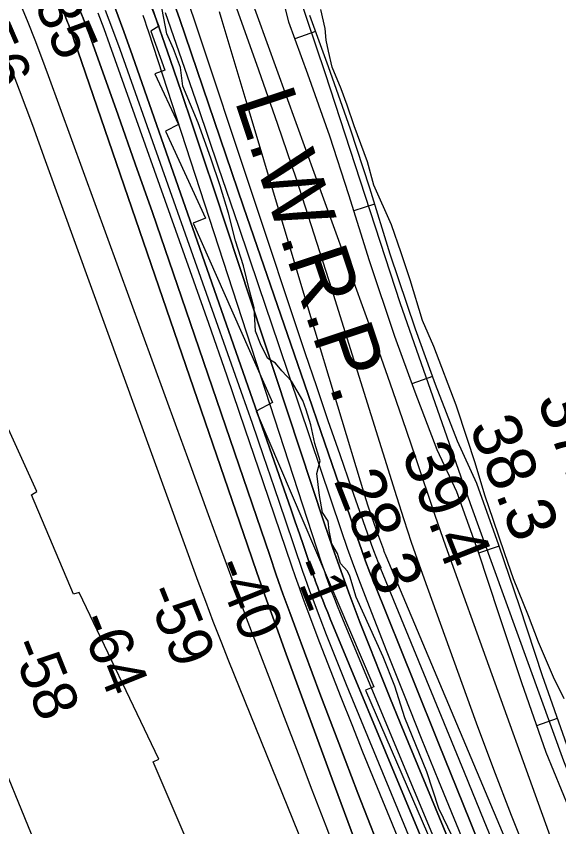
# Model space of a CAD drawing. Extents: x 3245246 to 3283090, y 806824 to 832173.
# Drawn here: x 3273263 to 3274008, y 812906 to 814018 of the extents above; entities that cross this region are included whole.
import ezdxf

# ---------------------------------------------------------------- set-up
doc = ezdxf.new("R2010")
doc.units = 0
for name, color, linetype in [('V-RIVR-EDGE', 7, 'Continuous'), ('V-RIVR-RANG', 7, 'Continuous'), ('V-ROAD-CNTR', 7, 'Continuous'), ('V-RRAP-RVMT', 7, 'Continuous'), ('V-SITE-VEGE', 7, 'Continuous'), ('V-TOPO-DPTH', 7, 'Continuous'), ('V-TOPO-MAJR', 7, 'Continuous'), ('V-TOPO-MINR', 7, 'Continuous'), ('V-TOPO-WATR', 7, 'Continuous'), ('V-TOPO-WATR-IDEN', 7, 'Continuous')]:
    doc.layers.add(name, color=color, linetype=linetype)

msp = doc.modelspace()

# ---------------------------------------------------------------- linework, layer by layer
at = {"layer": 'V-RIVR-EDGE'}
for points in [[(3273543.3, 813785.4), (3273530.4, 813823.2), (3273513.1, 813871.9), (3273491.9, 813922), (3273488.5, 813947.6), (3273479, 813973.3), (3273469.9, 813993.8), (3273461.4, 814039.4)], [(3273862.3, 812892.2), (3273843.3, 812930.9), (3273826.9, 812981.4), (3273796.7, 813055.3), (3273782.9, 813098.9), (3273766.9, 813139.3), (3273730.1, 813221.1), (3273721.1, 813249.8), (3273718.1, 813256.8), (3273708.5, 813267.3), (3273704.2, 813280.7), (3273696.4, 813294.2), (3273693, 813312.5), (3273691.3, 813325.1), (3273683.5, 813337.3), (3273679.6, 813360.3), (3273675.8, 813390.8), (3273680.6, 813408.2), (3273673.3, 813431.7), (3273667.7, 813457.3), (3273661.2, 813478.2), (3273656.5, 813490.8), (3273640.9, 813517.4), (3273627.9, 813531.7), (3273619.2, 813542.2), (3273608.8, 813548.7), (3273599.3, 813566.2), (3273591.5, 813586.2), (3273589.9, 813617.9), (3273583.4, 813641.8), (3273575.2, 813675.8), (3273564, 813710.1), (3273554.5, 813748), (3273543.3, 813785.4)]]:
    msp.add_lwpolyline(points, dxfattribs=at)
at = {"layer": 'V-ROAD-CNTR'}
for p, q in [((3273673.9, 813997.3), (3273645.8, 813987)), ((3273755.2, 813760.1), (3273726.5, 813751.2)), ((3273834.6, 813523.9), (3273806.4, 813513.6)), ((3273926.2, 813291.1), (3273897.8, 813281.5)), ((3274006.1, 813054.4), (3273977.8, 813044.4))]:
    msp.add_line(p, q, dxfattribs=at)
for points in [[(3272963.2, 815560), (3273122.6, 815224.6), (3273142.4, 815191.5), (3273353.7, 814953), (3273395.5, 814898.7), (3273440.1, 814822.1), (3273495.1, 814628), (3273529.1, 814569.5), (3273546.4, 814539.7), (3273596.6, 814463.2), (3273619.7, 814423.1), (3273629.1, 814390.7), (3273626, 814137.4), (3273649.7, 814051), (3273687.4, 813939.7), (3273789.9, 813625.3), (3273886.7, 813349.6), (3274014.5, 812996.5), (3274076.4, 812840.6), (3274213.5, 812549), (3274312.6, 812373.1), (3274357.1, 812286.8), (3274388.1, 812205.1)], [(3273619.3, 814081), (3273637.1, 814010.7), (3273663.2, 813939.3), (3273693.3, 813854), (3273719.6, 813773.4), (3273747.8, 813682.8), (3273782.6, 813579.1), (3273810.4, 813502.8), (3273840.9, 813423.6), (3273867.5, 813366.1), (3273897.3, 813283.1), (3273925.6, 813198.7), (3273956.8, 813104), (3273990.5, 813008.1), (3274022.2, 812931.4), (3274057.7, 812851.2), (3274092.4, 812770.8), (3274125.3, 812695.8), (3274162.2, 812620.9), (3274195.5, 812556.9), (3274241.3, 812467.3), (3274278, 812399.3), (3274306, 812345.1)], [(3273665.8, 814019.6), (3273691.4, 813949.4), (3273721.7, 813863.6), (3273748.2, 813782.5), (3273776.3, 813692), (3273810.9, 813589), (3273838.4, 813513.3), (3273868.5, 813435.3), (3273895.3, 813377.5), (3273925.6, 813292.9), (3273954.1, 813208.2), (3273985.2, 813113.7), (3274018.6, 813018.8), (3274049.7, 812943.2), (3274085.2, 812863.3), (3274119.9, 812782.8), (3274152.5, 812708.4), (3274189, 812634.4), (3274222.1, 812570.7), (3274267.8, 812481.3), (3274304.5, 812413.3), (3274332.6, 812358.9)]]:
    msp.add_lwpolyline(points, dxfattribs=at)
at = {"layer": 'V-RRAP-RVMT'}
for p, q in [((3273402.3, 814146.2), (3273459.1, 814004.7)), ((3273402.3, 814146.2), (3273459.1, 814004.7)), ((3273459.1, 814004.7), (3273448, 813997.6)), ((3273459.1, 814004.7), (3273448, 813997.6)), ((3273448, 813997.6), (3273467.1, 813944)), ((3273448, 813997.6), (3273467.1, 813944)), ((3273467.1, 813944), (3273453.5, 813939)), ((3273467.1, 813944), (3273453.5, 813939)), ((3273453.5, 813939), (3273485.8, 813869.4)), ((3273453.5, 813939), (3273485.8, 813869.4)), ((3273485.8, 813869.4), (3273468.2, 813860.5)), ((3273485.8, 813869.4), (3273468.2, 813860.5)), ((3273468.2, 813860.5), (3273523.1, 813741)), ((3273468.2, 813860.5), (3273523.1, 813741)), ((3273523.1, 813741), (3273506.2, 813734.1)), ((3273523.1, 813741), (3273506.2, 813734.1)), ((3273506.2, 813734.1), (3273615, 813487.9)), ((3273506.2, 813734.1), (3273615, 813487.9)), ((3273615, 813487.9), (3273592.4, 813476.1)), ((3273615, 813487.9), (3273592.4, 813476.1)), ((3273291.5, 813365.8), (3273241.2, 813476.5)), ((3273291.5, 813365.8), (3273241.2, 813476.5)), ((3273592.4, 813476.1), (3273754, 813098.1)), ((3273592.4, 813476.1), (3273754, 813098.1)), ((3273284, 813361.6), (3273291.5, 813365.8)), ((3273284, 813361.6), (3273291.5, 813365.8)), ((3273341.7, 813225.2), (3273284, 813361.6)), ((3273341.7, 813225.2), (3273284, 813361.6)), ((3273349.5, 813227.5), (3273341.7, 813225.2)), ((3273349.5, 813227.5), (3273341.7, 813225.2)), ((3273459.1, 812998.5), (3273349.5, 813227.5)), ((3273459.1, 812998.5), (3273349.5, 813227.5)), ((3273754, 813098.1), (3273742.6, 813093.2)), ((3273754, 813098.1), (3273742.6, 813093.2)), ((3273742.6, 813093.2), (3273950.8, 812614.6)), ((3273742.6, 813093.2), (3273950.8, 812614.6)), ((3273451.3, 812994.9), (3273459.1, 812998.5)), ((3273451.3, 812994.9), (3273459.1, 812998.5)), ((3273556.4, 812749), (3273451.3, 812994.9)), ((3273556.4, 812749), (3273451.3, 812994.9))]:
    msp.add_line(p, q, dxfattribs=at)
at = {"layer": 'V-SITE-VEGE'}
for p, q in [((3273687.3, 814001.3), (3273681.3, 814027.3)), ((3273688.5, 813985.3), (3273687.3, 814001.3)), ((3273692.1, 813970.4), (3273688.5, 813985.3)), ((3273696.9, 813948.2), (3273692.1, 813970.4)), ((3273709.1, 813918.5), (3273696.9, 813948.2)), ((3273717.6, 813896.2), (3273709.1, 813918.5)), ((3273727.3, 813867.8), (3273717.6, 813896.2)), ((3273745.6, 813818.4), (3273727.3, 813867.8)), ((3273754, 813786.2), (3273745.6, 813818.4)), ((3273778.4, 813731.8), (3273754, 813786.2)), ((3273791.8, 813693.5), (3273778.4, 813731.8)), ((3273803.9, 813656.4), (3273791.8, 813693.5)), ((3273820.9, 813600.8), (3273803.9, 813656.4)), ((3273836.8, 813564.9), (3273820.9, 813600.8)), ((3273867.2, 813484.5), (3273836.8, 813564.9)), ((3273883, 813437.5), (3273867.2, 813484.5)), ((3273892.7, 813406.6), (3273883, 813437.5)), ((3273907.2, 813359.6), (3273892.7, 813406.6)), ((3273918.2, 813327.5), (3273907.2, 813359.6)), ((3273934, 813280.5), (3273918.2, 813327.5)), ((3273946.1, 813245.9), (3273934, 813280.5)), ((3273966.8, 813195.2), (3273946.1, 813245.9)), ((3273980.2, 813159.3), (3273966.8, 813195.2)), ((3274000.9, 813111.1), (3273980.2, 813159.3)), ((3274015.6, 813081.4), (3274000.9, 813111.1))]:
    msp.add_line(p, q, dxfattribs=at)
at = {"layer": 'V-TOPO-DPTH'}
for points in [[(3273479, 814038), (3273487.1, 814014.9), (3273575.4, 813756.8), (3273603.2, 813675.7), (3273631, 813594.6), (3273658.8, 813513.6), (3273686.7, 813432.5), (3273731.6, 813301.9), (3273737.2, 813286.2), (3273742.9, 813270.5), (3273748.8, 813254.9), (3273755, 813239.4), (3273809.5, 813103.7), (3273843, 813020.4), (3273876.7, 812937.1), (3273910.4, 812853.9), (3273944.3, 812770.7), (3273950.3, 812755.9), (3273986.8, 812665.2), (3274022.7, 812574.3), (3274057.7, 812483), (3274092.2, 812391.5), (3274162.4, 812202.5), (3274127.9, 812202.5)], [(3273350.5, 814026.6), (3273355, 814015.3), (3273359.3, 814003.9), (3273363.5, 813992.5), (3273402.9, 813882.2), (3273426.5, 813815.6), (3273450, 813748.8), (3273473.2, 813682), (3273496.1, 813615.2), (3273611.2, 813278), (3273620.2, 813251.8), (3273629.4, 813225.7), (3273638.8, 813199.7), (3273648.4, 813173.7), (3273680.1, 813088.7), (3273705.9, 813020.4), (3273732, 812952.1), (3273758.7, 812884.2)], [(3273350.5, 814026.6), (3273355, 814015.3), (3273359.3, 814003.9), (3273363.5, 813992.5), (3273402.9, 813882.2), (3273426.5, 813815.6), (3273450, 813748.8), (3273473.2, 813682), (3273496.1, 813615.2), (3273611.2, 813278), (3273620.2, 813251.8), (3273629.4, 813225.7), (3273638.8, 813199.7), (3273648.4, 813173.7), (3273680.1, 813088.7), (3273705.9, 813020.4), (3273732, 812952.1), (3273758.7, 812884.2)], [(3273881.7, 812661.1), (3273739.3, 813008.2), (3273724.2, 813045.6), (3273709.2, 813083.1), (3273694.6, 813120.7), (3273680.2, 813158.4), (3273662.7, 813204.7), (3273657.2, 813219.3), (3273651.9, 813234), (3273646.7, 813248.8), (3273641.6, 813263.6), (3273602.4, 813379.1), (3273577.6, 813451.7), (3273552.7, 813524.1), (3273527.4, 813596.5), (3273501.9, 813668.8), (3273391.6, 813979.1), (3273383.7, 814000.8), (3273375.6, 814022.5)], [(3273881.7, 812661.1), (3273739.3, 813008.2), (3273724.2, 813045.6), (3273709.2, 813083.1), (3273694.6, 813120.7), (3273680.2, 813158.4), (3273662.7, 813204.7), (3273657.2, 813219.3), (3273651.9, 813234), (3273646.7, 813248.8), (3273641.6, 813263.6), (3273602.4, 813379.1), (3273577.6, 813451.7), (3273552.7, 813524.1), (3273527.4, 813596.5), (3273501.9, 813668.8), (3273391.6, 813979.1), (3273383.7, 814000.8), (3273375.6, 814022.5)], [(3273398.5, 814030.7), (3273410.7, 813997.4), (3273422.7, 813964), (3273640.5, 813340.9), (3273646.2, 813324.5), (3273651.9, 813308.1), (3273657.5, 813291.7), (3273663.1, 813275.2), (3273671.9, 813249.1), (3273673.1, 813245.7), (3273674.3, 813242.3), (3273675.5, 813238.9), (3273676.8, 813235.5), (3273680.7, 813225.2), (3273684, 813216.7), (3273687.4, 813208.3), (3273690.8, 813199.8), (3273694.2, 813191.4), (3273898.6, 812700.7)], [(3273898.6, 812700.7), (3273694.2, 813191.4), (3273690.8, 813199.8), (3273687.4, 813208.3), (3273684, 813216.7), (3273680.7, 813225.2), (3273676.8, 813235.5), (3273675.5, 813238.9), (3273674.3, 813242.3), (3273673.1, 813245.7), (3273671.9, 813249.1), (3273663.1, 813275.2), (3273657.5, 813291.7), (3273651.9, 813308.1), (3273646.2, 813324.5), (3273640.5, 813340.9), (3273422.7, 813964), (3273410.7, 813997.4), (3273398.5, 814030.7)], [(3273449.5, 814031.1), (3273474.5, 813958.6), (3273489.9, 813913.7), (3273505.2, 813868.7), (3273520.3, 813823.6), (3273535.3, 813778.6), (3273686.1, 813323), (3273697.4, 813289.7), (3273709.1, 813256.4), (3273721.2, 813223.3), (3273733.7, 813190.4), (3273735, 813186.8), (3273748.6, 813152.2), (3273762.3, 813117.6), (3273776.2, 813083.1), (3273790.3, 813048.7), (3273917.2, 812742.5), (3273954, 812652.6), (3273990.2, 812562.5), (3274025.5, 812472.1), (3274060.3, 812381.4), (3274124.2, 812212.2), (3274127.9, 812202.5)], [(3274127.9, 812202.5), (3274124.2, 812212.2), (3274060.3, 812381.4), (3274025.5, 812472.1), (3273990.2, 812562.5), (3273954, 812652.6), (3273917.2, 812742.5), (3273790.3, 813048.7), (3273776.2, 813083.1), (3273762.3, 813117.6), (3273748.6, 813152.2), (3273735, 813186.8), (3273733.7, 813190.4), (3273721.2, 813223.3), (3273709.1, 813256.4), (3273697.4, 813289.7), (3273686.1, 813323), (3273535.3, 813778.6), (3273520.3, 813823.6), (3273505.2, 813868.7), (3273489.9, 813913.7), (3273474.5, 813958.6), (3273449.5, 814031.1)], [(3273727.7, 812888.4), (3273700.1, 812962.6), (3273633.9, 813142.7), (3273620.3, 813180), (3273606.9, 813217.4), (3273593.7, 813254.8), (3273580.7, 813292.4), (3273347.6, 813970.8), (3273345.5, 813977), (3273343.3, 813983.2), (3273341.1, 813989.4), (3273338.9, 813995.6), (3273335.2, 814005.9), (3273334.8, 814007), (3273334.4, 814008), (3273334, 814009), (3273333.6, 814010), (3273329.7, 814019.5)], [(3273329.7, 814019.5), (3273333.6, 814010), (3273334, 814009), (3273334.4, 814008), (3273334.8, 814007), (3273335.2, 814005.9), (3273338.9, 813995.6), (3273341.1, 813989.4), (3273343.3, 813983.2), (3273345.5, 813977), (3273347.6, 813970.8), (3273580.7, 813292.4), (3273593.7, 813254.8), (3273606.9, 813217.4), (3273620.3, 813180), (3273633.9, 813142.7), (3273700.1, 812962.6), (3273727.7, 812888.4)]]:
    msp.add_lwpolyline(points, dxfattribs=at)
at = {"layer": 'V-TOPO-MAJR'}
for points in [[(3273968.3, 812858.1), (3273943.2, 812921.2), (3273919, 812984.6), (3273895.3, 813048.2), (3273827.7, 813234.2), (3273816.7, 813265.1), (3273806, 813296.1), (3273795.7, 813327.2), (3273785.7, 813358.5), (3273696.5, 813643.6), (3273672.4, 813719.1), (3273647.8, 813794.4), (3273622.2, 813869.4), (3273596.1, 813944.2), (3273552.2, 814067.6)], [(3273749.8, 812745.7), (3273688.6, 812906.5), (3273669.6, 812956.2), (3273650.6, 813005.9), (3273631.7, 813055.7), (3273612.7, 813105.4), (3273579.5, 813192.2), (3273577.1, 813198.5), (3273574.7, 813204.9), (3273572.4, 813211.2), (3273570, 813217.5), (3273544.2, 813287.7), (3273529, 813329.1), (3273513.8, 813370.5), (3273498.6, 813412), (3273483.5, 813453.4), (3273307.4, 813936.6), (3273298.3, 813961.1), (3273289, 813985.5), (3273279.4, 814009.7), (3273269.6, 814033.9)]]:
    msp.add_lwpolyline(points, dxfattribs=at)
at = {"layer": 'V-TOPO-MINR'}
for points in [[(3273791.2, 812550.4), (3273555.1, 813133), (3273544.3, 813160.2), (3273533.6, 813187.5), (3273523.3, 813214.9), (3273513.1, 813242.4), (3273303.5, 813819.7), (3273294.6, 813844.1), (3273285.7, 813868.4), (3273276.6, 813892.6), (3273267.5, 813916.9), (3273251.7, 813958.7), (3273250.4, 813962), (3273249.2, 813965.3), (3273247.8, 813968.6), (3273246.5, 813971.8), (3273070.8, 814390.2)], [(3274000.4, 812881.9), (3273980.1, 812937.7), (3273853.1, 813290.9), (3273849.4, 813301.4), (3273845.7, 813311.9), (3273842.1, 813322.4), (3273838.5, 813332.9), (3273811.4, 813413.4), (3273794.1, 813464.1), (3273776.6, 813514.8), (3273758.7, 813565.3), (3273740.6, 813615.8), (3273581.2, 814055.2)], [(3272883.6, 814035.1), (3272898, 814013.2), (3272912.1, 813991.1), (3272925.4, 813968.6), (3272937.6, 813945.4), (3272949, 813921.9), (3272974.6, 813865.2), (3272977.7, 813858.1), (3272980.7, 813850.9), (3272983.4, 813843.6), (3272986, 813836.3), (3273005.3, 813779.4), (3273017.2, 813743.5), (3273028.8, 813707.4), (3273039.8, 813671.3), (3273050.6, 813635), (3273216.9, 813058.6), (3273468.5, 812443.6), (3273480.3, 812413.7), (3273491.7, 812383.6), (3273502.3, 812353.3), (3273512.4, 812322.8), (3273535.6, 812250.2), (3273550.3, 812202.8)], [(3274162.4, 812202.5), (3274092.2, 812391.5), (3274057.7, 812483), (3274022.7, 812574.3), (3273986.8, 812665.2), (3273950.3, 812755.9), (3273944.3, 812770.7), (3273910.4, 812853.9), (3273876.7, 812937.1), (3273843, 813020.4), (3273809.5, 813103.7), (3273755, 813239.4), (3273748.8, 813254.9), (3273742.9, 813270.5), (3273737.2, 813286.2), (3273731.6, 813301.9), (3273686.7, 813432.5), (3273658.8, 813513.6), (3273631, 813594.6), (3273603.2, 813675.7), (3273575.4, 813756.8), (3273487.1, 814014.9), (3273479, 814038)], [(3274180, 812202.5), (3274090.5, 812446.1), (3274065.4, 812513.4), (3274039.9, 812580.5), (3274013.7, 812647.5), (3273987.1, 812714.2), (3273960.1, 812780.8), (3273933.1, 812847.4), (3273905.9, 812913.9), (3273878.7, 812980.4), (3273763.7, 813260), (3273760.4, 813268.2), (3273757.2, 813276.4), (3273754.1, 813284.7), (3273751.1, 813293.1), (3273724.1, 813369.5), (3273707.8, 813416.1), (3273691.6, 813462.8), (3273675.7, 813509.6), (3273660, 813556.4), (3273510.7, 814004.5), (3273499.6, 814036.9)], [(3273758.7, 812884.2), (3273732, 812952.1), (3273705.9, 813020.4), (3273680.1, 813088.7), (3273648.4, 813173.7), (3273638.8, 813199.7), (3273629.4, 813225.7), (3273620.2, 813251.8), (3273611.2, 813278), (3273496.1, 813615.2), (3273473.2, 813682), (3273450, 813748.8), (3273426.5, 813815.6), (3273402.9, 813882.2), (3273363.5, 813992.5), (3273359.3, 814003.9), (3273355, 814015.3), (3273350.5, 814026.6)], [(3273881.7, 812661.1), (3273739.3, 813008.2), (3273724.2, 813045.6), (3273709.2, 813083.1), (3273694.6, 813120.7), (3273680.2, 813158.4), (3273662.7, 813204.7), (3273657.2, 813219.3), (3273651.9, 813234), (3273646.7, 813248.8), (3273641.6, 813263.6), (3273602.4, 813379.1), (3273577.6, 813451.7), (3273552.7, 813524.1), (3273527.4, 813596.5), (3273501.9, 813668.8), (3273391.6, 813979.1), (3273383.7, 814000.8), (3273375.6, 814022.5)], [(3273890.2, 812680.9), (3273716.6, 813100.8), (3273707.3, 813123.6), (3273698.2, 813146.4), (3273689.2, 813169.2), (3273680.4, 813192.2), (3273669.8, 813220.1), (3273666.4, 813229.1), (3273663.1, 813238.2), (3273659.9, 813247.3), (3273656.7, 813256.4), (3273633, 813326.7), (3273617.9, 813370.9), (3273602.7, 813415.1), (3273587.4, 813459.2), (3273571.8, 813503.3), (3273405.7, 813972.3), (3273395.9, 813999.3), (3273385.8, 814026.2)], [(3273898.6, 812700.7), (3273694.2, 813191.4), (3273690.8, 813199.8), (3273687.4, 813208.3), (3273684, 813216.7), (3273680.7, 813225.2), (3273676.8, 813235.5), (3273675.5, 813238.9), (3273674.3, 813242.3), (3273673.1, 813245.7), (3273671.9, 813249.1), (3273663.1, 813275.2), (3273657.5, 813291.7), (3273651.9, 813308.1), (3273646.2, 813324.5), (3273640.5, 813340.9), (3273422.7, 813964), (3273410.7, 813997.4), (3273398.5, 814030.7)], [(3274145, 812202.5), (3274081.9, 812371), (3274044.3, 812469.8), (3274006.1, 812568.3), (3273967, 812666.5), (3273927.3, 812764.4), (3273867.7, 812909.4), (3273843.6, 812968.3), (3273819.8, 813027.2), (3273796.2, 813086.2), (3273772.7, 813145.3), (3273744.9, 813216), (3273735.7, 813239.9), (3273726.8, 813263.8), (3273718.2, 813287.8), (3273709.8, 813312), (3273623.9, 813567.1), (3273596.4, 813648.4), (3273568.8, 813729.8), (3273541, 813811.1), (3273513.2, 813892.3), (3273468.3, 814023)], [(3273954.1, 812843.3), (3273770.9, 813277.3), (3273770.1, 813279.4), (3273769.2, 813281.5), (3273768.4, 813283.6), (3273767.7, 813285.7), (3273759.6, 813307.7), (3273755, 813320.9), (3273750.4, 813334.1), (3273746.1, 813347.4), (3273742, 813360.7), (3273667.8, 813605.6), (3273646.1, 813677.3), (3273624.5, 813749.1), (3273603, 813820.9), (3273581.6, 813892.7), (3273546.1, 814012), (3273542.4, 814024.2)], [(3273727.7, 812888.4), (3273700.1, 812962.6), (3273633.9, 813142.7), (3273620.3, 813180), (3273606.9, 813217.4), (3273593.7, 813254.8), (3273580.7, 813292.4), (3273347.6, 813970.8), (3273345.5, 813977), (3273343.3, 813983.2), (3273341.1, 813989.4), (3273338.9, 813995.6), (3273335.2, 814005.9), (3273334.8, 814007), (3273334.4, 814008), (3273334, 814009), (3273333.6, 814010), (3273329.7, 814019.5)], [(3274110.9, 812202.5), (3274110.4, 812203.8), (3274088.6, 812261.1), (3274038.9, 812391.6), (3274007, 812474.3), (3273974.5, 812556.8), (3273941.2, 812639.1), (3273907.5, 812721.1), (3273712.4, 813188.6), (3273708.3, 813198.5), (3273704.3, 813208.4), (3273700.4, 813218.3), (3273696.6, 813228.2), (3273692.9, 813238.2), (3273689.2, 813248.2), (3273685.8, 813258.3), (3273682.4, 813268.4), (3273445.1, 813996.4), (3273442.6, 814004), (3273440.1, 814011.6), (3273437.5, 814019.2)]]:
    msp.add_lwpolyline(points, dxfattribs=at)
at = {"layer": 'V-TOPO-WATR'}
msp.add_lwpolyline([(3274127.9, 812202.5), (3274124.2, 812212.2), (3274060.3, 812381.4), (3274025.5, 812472.1), (3273990.2, 812562.5), (3273954, 812652.6), (3273917.2, 812742.5), (3273790.3, 813048.7), (3273776.2, 813083.1), (3273762.3, 813117.6), (3273748.6, 813152.2), (3273735, 813186.8), (3273733.7, 813190.4), (3273721.2, 813223.3), (3273709.1, 813256.4), (3273697.4, 813289.7), (3273686.1, 813323), (3273535.3, 813778.6), (3273520.3, 813823.6), (3273505.2, 813868.7), (3273489.9, 813913.7), (3273474.5, 813958.6), (3273449.5, 814031.1)], dxfattribs=at)

# ---------------------------------------------------------------- texts
at = {"layer": 'V-RIVR-RANG'}
for s, height, rotation, p in [('-35', 60, 293.4204, (3273276.7, 814060.4)), ('-56', 60, 293.4204, (3273185.9, 814018.3)), ('37.2', 67, 291.5083, (3273977.5, 813492)), ('38.3', 67, 291.5083, (3273884.5, 813455.1)), ('39.4', 67, 291.5083, (3273791.6, 813418.2)), ('28.3', 67, 291.5083, (3273698.6, 813381.3)), ('-40', 60, 291.7952, (3273533.3, 813264)), ('-1', 60, 291.7952, (3273640.8, 813264.5)), ('-59', 60, 291.7952, (3273440, 813228)), ('-64', 60, 291.7952, (3273347.7, 813189.3)), ('-58', 60, 291.7952, (3273253.8, 813154.9))]:
    msp.add_text(s, height=height, rotation=rotation, dxfattribs=at).set_placement(p)
at = {"layer": 'V-TOPO-WATR-IDEN'}
msp.add_text('L.W.R.P.', height=83, rotation=288.3452, dxfattribs=at).set_placement((3273562.5, 813903))

doc.saveas('drawing.dxf')
